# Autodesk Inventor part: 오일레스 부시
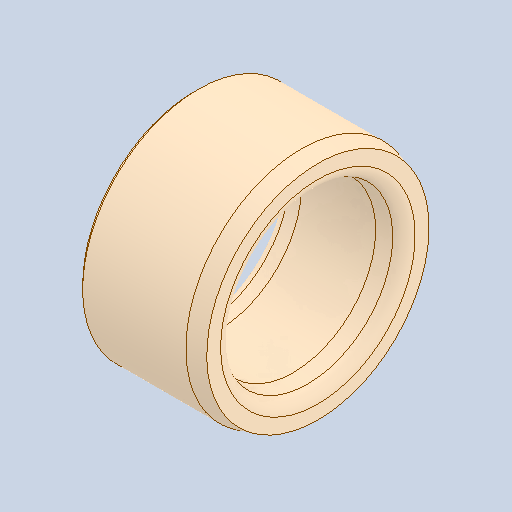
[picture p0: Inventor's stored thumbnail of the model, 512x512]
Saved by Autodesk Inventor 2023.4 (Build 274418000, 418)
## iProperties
Created: 2024-05
Part Number: 오일레스 부시
Material: 구리, 합금
Document SubType Name: Modeling
Designer: edu-40
Density: 8.92 g/cm^3
Appearance: 기본값
Author: jhkim
Sending System: Autodesk Inventor 2025
Preprocessor: ST-DEVELOPER v20
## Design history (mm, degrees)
feature "솔리드1"
node "솔리드2"
